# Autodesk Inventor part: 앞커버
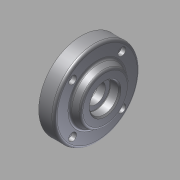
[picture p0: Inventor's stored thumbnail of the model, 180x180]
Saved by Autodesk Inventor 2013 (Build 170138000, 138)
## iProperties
Company: 한국ATC센터
Created: 2015-12
Part Number: 앞커버
Document SubType Name: Modeling
Designer: 앞커버
Density: 2.71 g/cm^3
Mass: 114.339 g
Surface Area: 117.889 cm^2
Volume: 42.1916 cm^3
Material: 일반
Author: mdu
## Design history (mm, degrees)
sketch "스케치1"
  geometry: L1 (-11.5, 0)-(11.5, 0); L2 (11.5, 0)-(11.5, 22.5); L3 (11.5, 22.5)-(6.5, 22.5); L4 (6.5, 22.5)-(6.5, 32.5); L5 (6.5, 32.5)-(-5.5, 32.5); L6 (-5.5, 32.5)-(-5.5, 21); L7 (-5.5, 21)-(-11.5, 18.202); L8 (-11.5, 18.202)-(-11.5, 0); 2 further points
  constraints: 16 end point, 3 parallel, 3 perpendicular, 1 coincident, 1 horizontal, 1 midpoint
  dimensions: "d0" = 23 distance of L1.start L1.end; "d1" = 65 diameter of L5 L1; "d2" = 45 diameter of L3 L1; "d3" = 42 diameter of L6.end L1; "d4" = 115 deg angle of L7 L6; "d5" = 12 distance of L4.end L5.end; "d6" = 5 distance of L2.end L3.end
revolve "회전1" sketch "스케치1" stored, may be unused: angle "d7" = 90 deg
sketch "스케치2"
  geometry: L1 (0, 0)-(32.5, 0); L2 (0, 0)-(18.738, 18.738); 1 further point
  constraints: 4 end point, 1 horizontal, 1 horizontal alignment, 1 other
  dimensions: "d8" = 45 deg angle of L1 L2; "d9" = 26.5 distance of L1.start L2.end
hole "구멍1" sketch "스케치2" at (18.738, 18.738) diameter "d10" = 3.4; stored, may be unused: countersink angle "d14" = 90 deg, drill point angle "d16" = 118 deg; dims "d11" = 6, "d12" = 6, "d13" = 3.3, "d15" = 8
fillet "모깎기1" dims "d20" = 2
hole "구멍2" diameter "d23" = 15; stored, may be unused: countersink angle "d27" = 90 deg, drill point angle "d29" = 118 deg; dims "d21" = 10, "d22" = 10, "d24" = 6, "d25" = 32, "d26" = 10, "d28" = 8
hole "구멍3" diameter "d32" = 22; stored, may be unused: countersink angle "d36" = 90 deg, drill point angle "d38" = 0 deg; dims "d30" = 10, "d31" = 10, "d33" = 6, "d34" = 32, "d35" = 10, "d37" = 7.3
chamfer "모따기1" distance "d39" = 1; stored, may be unused: second distance "d40" = 2, angle "d41" = 45 deg
fillet "모깎기2" dims "d42" = 0.3
node "솔리드1"
pattern_circular "원형 패턴1" dims angle "d18" = 360 deg
